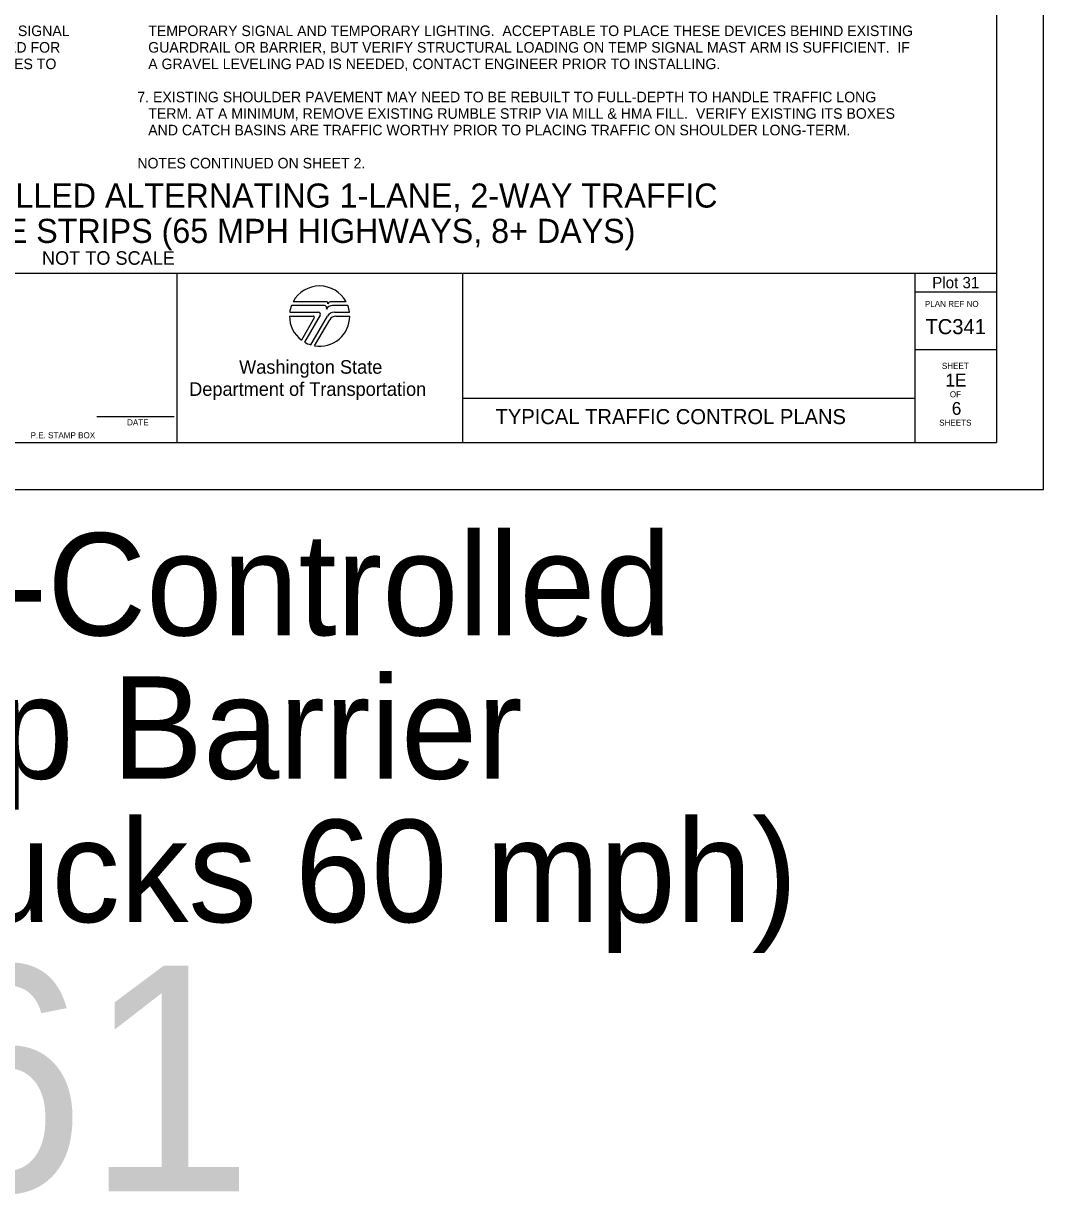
# Model space of a CAD drawing. Extents: x 99977 to 100176, y 99905 to 100011.
# Drawn here: x 100009.29 to 100016.06, y 99905.01 to 99912.78 of the extents above; entities that cross this region are included whole.
import ezdxf

# ---------------------------------------------------------------- set-up
doc = ezdxf.new("R2010")
doc.units = 0
for name, color, linetype in [('SH_DE_DetailHeading1Text', 7, 'Continuous'), ('SH_GI_GeneralNotesBodyText', 7, 'Continuous'), ('SH_GI_PlotLimits', 7, 'Continuous'), ('SH_GI_SheetBorder', 7, 'Continuous'), ('SH_GI_SheetLocationText', 7, 'Continuous'), ('SH_GI_SheetTextInCells', 7, 'Continuous'), ('SH_GI_TitleBlockText', 7, 'Continuous'), ('SH_GI_WSDOTLogo', 7, 'Continuous')]:
    doc.layers.add(name, color=color, linetype=linetype)

msp = doc.modelspace()

# ---------------------------------------------------------------- linework, layer by layer
at = {"layer": 'SH_GI_PlotLimits'}
msp.add_lwpolyline([(99999.0625, 99909.6875), (100016.0625, 99909.6875), (100016.0625, 99920.6875), (99999.0625, 99920.6875)], close=True, dxfattribs=at)
at = {"layer": 'SH_GI_SheetBorder'}
for p, q in [((100015.75, 99920.375), (100015.75, 99910)), ((100000, 99911.1259), (100015.75, 99911.1259)), ((100010.3089, 99911.1259), (100010.3089, 99910)), ((100012.2055, 99911.1259), (100012.2055, 99910)), ((100015.2079, 99911.1259), (100015.2079, 99910)), ((100015.2079, 99911.0008), (100015.75, 99911.0008)), ((100015.2079, 99910.6176), (100015.75, 99910.6176)), ((100012.2055, 99910.2955), (100015.2079, 99910.2955)), ((100009.7797, 99910.1733), (100010.2914, 99910.1733)), ((100000, 99910), (100015.75, 99910))]:
    msp.add_line(p, q, dxfattribs=at)
at = {"layer": 'SH_GI_WSDOTLogo'}
for p, q in [((100011.303, 99910.9354), (100011.0815, 99910.9354)), ((100011.433, 99910.9354), (100011.3351, 99910.9354)), ((100011.0572, 99910.84), (100011.2148, 99910.84)), ((100011.059, 99910.8661), (100011.2496, 99910.8661)), ((100011.2894, 99910.9094), (100011.0697, 99910.9094)), ((100011.261, 99910.8464), (100011.1567, 99910.6672)), ((100011.1989, 99910.6487), (100011.3089, 99910.839)), ((100011.343, 99910.9094), (100011.3429, 99910.9094)), ((100011.4448, 99910.9094), (100011.343, 99910.9094)), ((100011.3558, 99910.8661), (100011.4555, 99910.8661)), ((100011.3655, 99910.8394), (100011.4572, 99910.8394)), ((100011.222, 99910.8277), (100011.1364, 99910.6807)), ((100011.2244, 99910.6428), (100011.3242, 99910.8156))]:
    msp.add_line(p, q, dxfattribs=at)
for centre, radius, start, end in [((100011.2572, 99910.84), 0.2, 28.47865, 151.53204), ((100011.303, 99910.9263), 0.00903, 329.87418, 90.00328), ((100011.3352, 99910.9066), 0.0287, 90.00721, 148.16763), ((100011.2572, 99910.84), 0.2, 179.99864, 232.84327), ((100011.2572, 99910.84), 0.2, 159.69598, 172.50569), ((100011.2149, 99910.8318), 0.0082, 329.74356, 90), ((100011.2572, 99910.84), 0.2, 260.54554, 359.80857), ((100011.2497, 99910.853), 0.0131, 329.76834, 90), ((100011.2894, 99910.8946), 0.0148, 327.8418, 89.99855), ((100011.3429, 99910.861), 0.0484, 89.99529, 147.82376), ((100011.3558, 99910.8119), 0.0542, 90, 149.99738), ((100011.3654, 99910.7918), 0.0476, 90, 150.05432), ((100011.2572, 99910.84), 0.2, 7.49431, 20.29406), ((100011.2572, 99910.84), 0.2, 239.79292, 253.0448)]:
    msp.add_arc(centre, radius, start, end, dxfattribs=at)

# ---------------------------------------------------------------- texts
at = {"layer": 'SH_DE_DetailHeading1Text'}
for s, height, p in [('SIMPLE TEMPORARY SIGNAL-CONTROLLED ALTERNATING 1-LANE, 2-WAY TRAFFIC', 0.16, (100005.196, 99911.5606)), ('25 WZSL + TEMP BARRIER + RUMBLE STRIPS (65 MPH HIGHWAYS, 8+ DAYS)', 0.16, (100005.441, 99911.3259)), ('NOT TO SCALE', 0.09, (100009.4141, 99911.1809))]:
    msp.add_text(s, height=height, rotation=360, dxfattribs=at).set_placement(p)
at = {"layer": 'SH_GI_GeneralNotesBodyText'}
for s, p in [(' THIS SIGNAL ', (100008.9894, 99912.6998)), ('TEMPORARY SIGNAL AND TEMPORARY LIGHTING.  ACCEPTABLE TO PLACE THESE DEVICES BEHIND EXISTING ', (100010.1197, 99912.6998)), ('  THE SIGNAL IS TIMED FOR ', (100008.272, 99912.5899)), ('GUARDRAIL OR BARRIER, BUT VERIFY STRUCTURAL LOADING ON TEMP SIGNAL MAST ARM IS SUFFICIENT.  IF ', (100010.1197, 99912.5899)), (' TO ALLOW BICYCLES TO ', (100008.3553, 99912.48)), ('A GRAVEL LEVELING PAD IS NEEDED, CONTACT ENGINEER PRIOR TO INSTALLING.', (100010.1197, 99912.48)), ('7. EXISTING SHOULDER PAVEMENT MAY NEED TO BE REBUILT TO FULL-DEPTH TO HANDLE TRAFFIC LONG ', (100010.0475, 99912.2602)), ('TERM. AT A MINIMUM, REMOVE EXISTING RUMBLE STRIP VIA MILL & HMA FILL.  VERIFY EXISTING ITS BOXES ', (100010.1197, 99912.1503)), ('AND CATCH BASINS ARE TRAFFIC WORTHY PRIOR TO PLACING TRAFFIC ON SHOULDER LONG-TERM.', (100010.1197, 99912.0404)), ('NOTES CONTINUED ON SHEET 2.', (100010.0475, 99911.8206))]:
    msp.add_text(s, height=0.07, rotation=360, dxfattribs=at).set_placement(p)
at = {"layer": 'SH_GI_SheetBorder'}
msp.add_text('PLAN REF NO', height=0.040032, dxfattribs=at).set_placement((100015.2747, 99910.9008))
at = {"layer": 'SH_GI_SheetLocationText'}
for s, height, p in [('Plot 31', 0.075, (100015.3235, 99911.025)), (' Temp Signal-Controlled', 0.68, (100003.7893, 99908.7191)), ('Alt Traffic w/ Temp Barrier', 0.68, (100002.0459, 99907.7671)), ('& Rumble Strips (65, Trucks 60 mph)', 0.68, (99999.4717, 99906.8151)), ('Plot 61', 1.5, (100004.5756, 99905.0267))]:
    msp.add_text(s, height=height, dxfattribs=at).set_placement(p)
at = {"layer": 'SH_GI_SheetTextInCells'}
for s, height, p in [('Washington State', 0.090072, (100010.7229, 99910.4571)), ('SHEET', 0.04003, (100015.3877, 99910.4896)), ('Department of Transportation', 0.090072, (100010.3916, 99910.3101)), ('OF', 0.04003, (100015.4406, 99910.3008)), ('DATE', 0.04003, (100009.9794, 99910.1141)), ('SHEETS', 0.04003, (100015.3698, 99910.112)), ('P.E. STAMP BOX', 0.040032, (100009.339, 99910.0286))]:
    msp.add_text(s, height=height, dxfattribs=at).set_placement(p)
at = {"layer": 'SH_GI_TitleBlockText'}
for s, height, p in [('TC341', 0.1, (100015.2784, 99910.72)), ('1E', 0.085, (100015.4116, 99910.3723)), ('TYPICAL TRAFFIC CONTROL PLANS', 0.1, (100012.4251, 99910.1224)), ('6', 0.085, (100015.4534, 99910.1843))]:
    msp.add_text(s, height=height, dxfattribs=at).set_placement(p)

doc.saveas('drawing.dxf')
